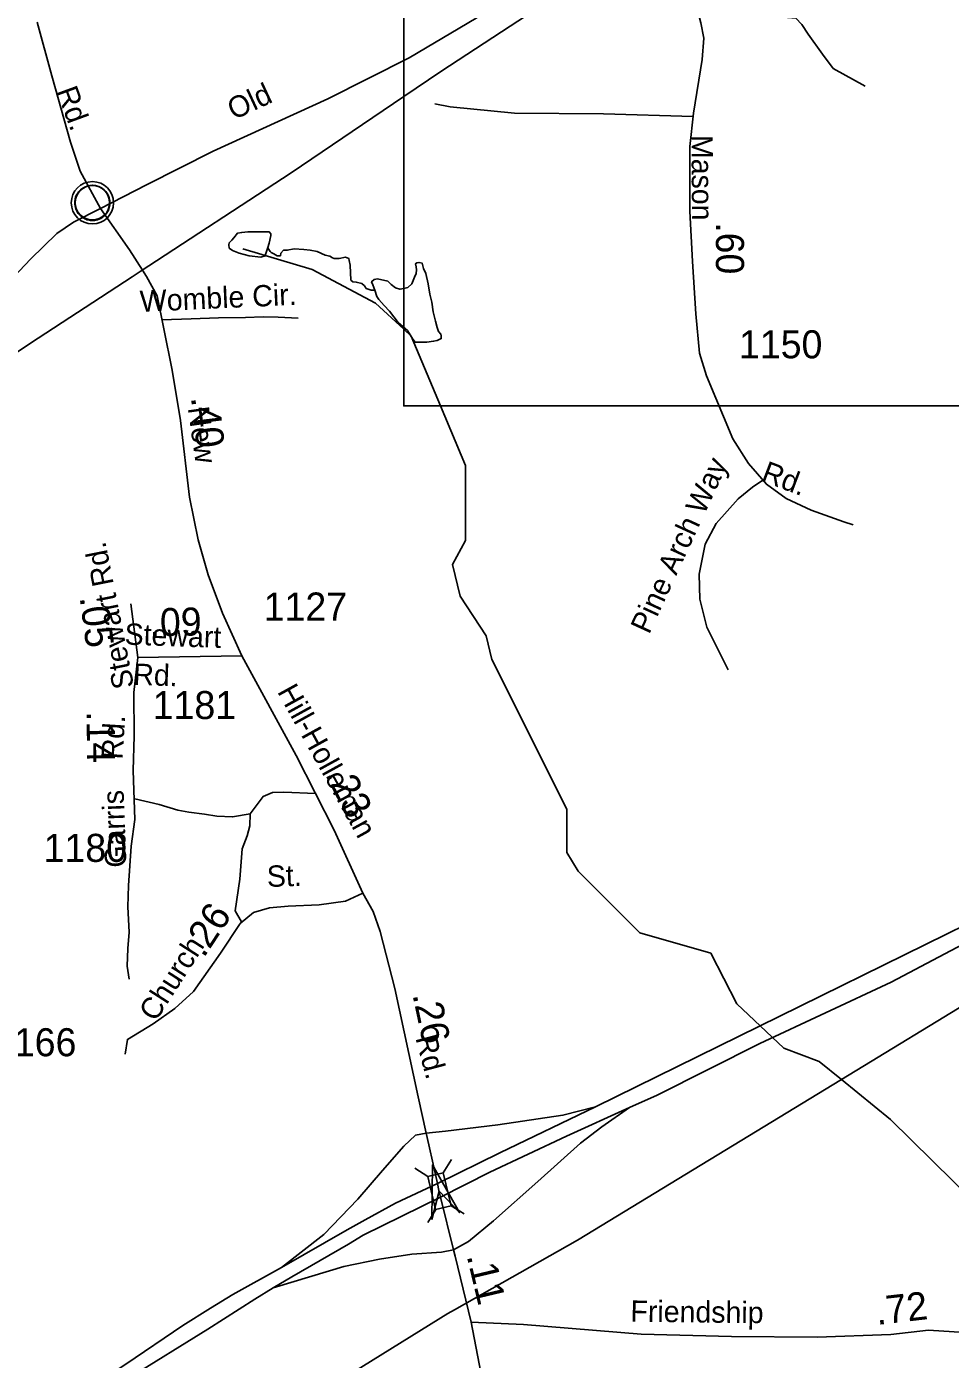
# Model space of a CAD drawing. Extents: x 2001466 to 2224147, y 644118 to 847247.
# Drawn here: x 2018793 to 2022908, y 697641 to 703581 of the extents above; entities that cross this region are included whole.
import ezdxf

# ---------------------------------------------------------------- set-up
doc = ezdxf.new("R2010")
doc.units = 0
for name, color, linetype in [('Exist Civil Demographics Community CELL', 7, 'Continuous'), ('Exist Hydrographic Misc Water Feature', 7, 'Continuous'), ('Exist Railroad Mainline', 7, 'Continuous'), ('Exist Road Non-System Type 51', 7, 'Continuous'), ('Exist Road Non-System Type 51 Label', 7, 'Continuous'), ('Exist Road Primary US Divided Attributed', 7, 'Continuous'), ('Exist Road Primary US Ramp 1 Lane  Attributed', 7, 'Continuous'), ('Exist Road Secondary Mileage Hundredths English Label', 7, 'Continuous'), ('Exist Road Secondary Structure Standard Bridge Attributed CELL', 7, 'Continuous'), ('Exist Road Secondary Structure Standard Bridge CELL', 7, 'Continuous'), ('Exist Road Secondary Type 51 Attributed', 7, 'Continuous'), ('Exist Road Secondary Type 51 Label', 7, 'Continuous'), ('Exist Road Secondary Type 51 Number Label', 7, 'Continuous'), ('Exist Utilities Electrical Transmission Line', 7, 'Continuous'), ('Map Preparation Inset Cut Line', 7, 'Continuous')]:
    doc.layers.add(name, color=color, linetype=linetype)

msp = doc.modelspace()

# ---------------------------------------------------------------- linework, layer by layer
at = {"layer": 'Exist Civil Demographics Community CELL'}
msp.add_lwpolyline([(2019008.1, 702808.4), (2019009.1, 702814), (2019010.9, 702820.6), (2019013.8, 702827.8), (2019016.7, 702833.5), (2019020.1, 702839.3), (2019023.8, 702844.4), (2019027.8, 702848.8), (2019032.4, 702853.4), (2019037.9, 702858), (2019043.3, 702861.6), (2019048.2, 702864.5), (2019053.3, 702866.9), (2019058.7, 702869.2), (2019064.4, 702871.1), (2019068.7, 702872.2), (2019073.5, 702872.9), (2019077.7, 702873.7), (2019084, 702873.9), (2019088.5, 702873.8), (2019094.1, 702873.6), (2019099, 702872.8), (2019103.9, 702871.8), (2019108.9, 702870.4), (2019114.1, 702868.5), (2019120.8, 702865.6), (2019127, 702862.1), (2019132.1, 702858.5), (2019137.3, 702854.5), (2019140.6, 702851.4), (2019144.7, 702847), (2019148.6, 702842.3), (2019151.6, 702837.7), (2019154.8, 702832.7), (2019157.2, 702827.5), (2019159.2, 702822.5), (2019160.8, 702817.5), (2019162.1, 702812.9), (2019163.2, 702806.9), (2019163.8, 702802.2), (2019164.1, 702796.2), (2019163.9, 702790.4), (2019163.3, 702784.7), (2019162.4, 702779.2), (2019160.7, 702773.1), (2019158.9, 702767.2), (2019156.6, 702762.2), (2019153.4, 702756.2), (2019150.1, 702750.8), (2019146.7, 702746.1), (2019142.4, 702741.4), (2019137.1, 702736.4), (2019132.1, 702732.3), (2019127.1, 702728.9), (2019122.8, 702726.4), (2019116, 702723.1), (2019108.8, 702720.4), (2019102.9, 702719), (2019096.3, 702717.7), (2019091.9, 702717.2), (2019087.4, 702716.9), (2019081.8, 702716.9), (2019077.5, 702717.3), (2019071.9, 702718.1), (2019066, 702719.4), (2019061.4, 702720.7), (2019056.2, 702722.6), (2019051.6, 702724.5), (2019047.7, 702726.8), (2019040.9, 702730.9), (2019035.3, 702735.1), (2019030.4, 702739.6), (2019025.9, 702744.5), (2019022.7, 702748.4), (2019019.8, 702752.6), (2019015.7, 702759.7), (2019014, 702763.3), (2019012.2, 702767.3), (2019009.7, 702775.5), (2019008.1, 702782.5), (2019007.4, 702787.7), (2019007.1, 702794), (2019007, 702798.7), (2019007.6, 702805.2)], close=True, dxfattribs=at)
for centre, radius in [((2019085.7, 702796), 94.3), ((2019085.5, 702796.3), 76.7)]:
    msp.add_circle(centre, radius, dxfattribs=at)
at = {"layer": 'Exist Hydrographic Misc Water Feature'}
for points in [[(2019867.4, 702596), (2019857.5, 702566.1), (2019855.5, 702560.1), (2019835.6, 702554.1), (2019783.5, 702560.1), (2019739.4, 702572), (2019709.5, 702584), (2019695.6, 702594), (2019693.5, 702608), (2019695.6, 702618), (2019707.5, 702630), (2019715.4, 702640), (2019731.4, 702660), (2019751.3, 702664), (2019777.4, 702666.1), (2019809.4, 702666.1), (2019837.5, 702666.1), (2019859.4, 702666.1), (2019873.3, 702666.1), (2019881.3, 702658.1), (2019881.3, 702650.1), (2019873.3, 702616.1), (2019867.4, 702596)], [(2020472.9, 702232.5), (2020347.6, 702348.9), (2020064.7, 702499), (2019755.6, 702590.6)], [(2019867.4, 702596), (2019871.5, 702588.2), (2019877.4, 702578.2), (2019881.5, 702574.1), (2019893.4, 702568.1), (2019909.4, 702560.1), (2019923.6, 702560.1)], [(2019923.6, 702560.1), (2019925.4, 702572.1), (2019937.3, 702584.2), (2019953.5, 702584.2), (2019985.3, 702590.2), (2020027.3, 702588.2), (2020055.4, 702584.2), (2020087.4, 702578.2), (2020123.3, 702562.3), (2020143.4, 702558.3), (2020155.5, 702550.3), (2020163.5, 702548.3), (2020185.4, 702548.3), (2020213.3, 702554.3), (2020227.5, 702548.3), (2020229.3, 702538.3), (2020233.4, 702518.3), (2020237.5, 702450.4)], [(2020343.5, 702406.5), (2020335.5, 702430.4), (2020329.6, 702444.4), (2020341.5, 702454.4), (2020355.4, 702456.4), (2020401.6, 702446.5), (2020417.5, 702432.5), (2020435.6, 702416.5), (2020455.5, 702410.5), (2020473.5, 702414.5), (2020491.6, 702418.5), (2020509.4, 702434.5), (2020521.3, 702464.5), (2020527.5, 702480.5), (2020529.3, 702496.5), (2020527.5, 702510.5), (2020525.4, 702524.5), (2020531.4, 702528.5), (2020541.4, 702530.5), (2020555.3, 702526.5), (2020561.3, 702502.5), (2020571.3, 702480.5), (2020581.6, 702434.6), (2020589.6, 702388.6), (2020597.6, 702352.6), (2020603.5, 702310.6), (2020609.5, 702286.6), (2020613.6, 702268.6), (2020621.6, 702240.6), (2020627.5, 702222.6), (2020637.6, 702210.7), (2020639.6, 702202.7), (2020639.6, 702190.7), (2020621.6, 702182.6), (2020605.6, 702178.6), (2020575.6, 702174.6), (2020563.5, 702174.6)], [(2020237.5, 702450.4), (2020245.5, 702444.3), (2020261.5, 702442.3), (2020285.5, 702436.4), (2020297.6, 702426.4), (2020305.6, 702414.4), (2020313.6, 702410.4), (2020327.5, 702406.4), (2020343.5, 702406.5)], [(2020563.5, 702174.6), (2020555.5, 702174.6), (2020551.7, 702174.6), (2020527.7, 702174.5), (2020523.6, 702174.6), (2020513.7, 702188.5), (2020489.7, 702226.5), (2020447.5, 702262.5), (2020409.6, 702312.5), (2020385.6, 702338.4), (2020361.6, 702364.4), (2020353.6, 702378.4), (2020343.5, 702406.5)], [(2020637.1, 701890.9), (2020506.5, 702201.3), (2020472.9, 702232.5)], [(2020748.5, 701290.8), (2020748.7, 701625.4), (2020637.1, 701890.9)], [(2022422.9, 698888.1), (2022324.5, 698968.5), (2022166.4, 699027.5), (2021957.5, 699225.3), (2021840.6, 699450.8), (2021524.6, 699542.5), (2021249.6, 699817.2), (2021199.6, 699900.3), (2021199.6, 700093.8), (2020865.6, 700760.2), (2020840.6, 700865.7), (2020723.7, 701041.9), (2020690.7, 701183.7), (2020748.5, 701290.8)], [(2023158.5, 698226.4), (2023108.4, 698250.4), (2022641.5, 698709.4), (2022422.9, 698888.1)]]:
    msp.add_lwpolyline(points, dxfattribs=at)
at = {"layer": 'Exist Railroad Mainline'}
for points in [[(2019262.5, 702465.7), (2019299.1, 702489.6), (2019971.3, 702930.1), (2020472.9, 703269.2), (2020637.8, 703380.6), (2021290.1, 703808.9), (2021599.5, 704013.4)], [(2014695.2, 699465.6), (2014957.6, 699637.9), (2015969.1, 700295.6), (2016972.6, 700965.2), (2017688.8, 701433.9), (2017826.9, 701523.3), (2018309.5, 701836.1), (2018810.1, 702169.9), (2019262.5, 702465.7)]]:
    msp.add_lwpolyline(points, dxfattribs=at)
at = {"layer": 'Exist Road Non-System Type 51'}
for points in [[(2021788.3, 703630.9), (2021904.1, 703630.9), (2021964, 703630.9), (2022039.8, 703634.8), (2022127.6, 703626.9), (2022219.4, 703618.9), (2022247.3, 703590.9), (2022275.3, 703547), (2022339.1, 703459.1), (2022387, 703395.2), (2022528.6, 703315.3)], [(2020611.9, 703236.7), (2020679, 703224), (2020966.8, 703195.2), (2021363.3, 703192), (2021762.2, 703180.9)], [(2019395.6, 702273.9), (2019525.3, 702279.3), (2019647.5, 702283.3), (2019767.3, 702285.3), (2019846.6, 702287.3), (2019912.9, 702286.4), (2020002.7, 702282.2)], [(2021918.3, 700714), (2021824, 700904.7), (2021792.6, 701028.6), (2021788.7, 701140.6), (2021816.2, 701274.3), (2021865.3, 701366.7), (2021963.5, 701476.8), (2022026.4, 701527.9), (2022072.9, 701559.7)], [(2019788.3, 700071.7), (2019710.2, 700058.5), (2019640.3, 700062.4), (2019584.3, 700070.3), (2019514.8, 700079.9), (2019466.2, 700089.2), (2019383.5, 700114.6), (2019274, 700139.2)], [(2020079.8, 700163.4), (2019938.3, 700168.3), (2019887.5, 700167.7), (2019846.2, 700149.1), (2019788.3, 700071.7)], [(2019788.3, 700071.7), (2019787.4, 700018.4), (2019774.7, 699973.6), (2019752.3, 699916.1), (2019742.7, 699781.7), (2019721.3, 699639.6), (2019749.4, 699591.4)], [(2019274, 700047.7), (2019258.8, 699928.9), (2019246.6, 699752.3), (2019243.6, 699657.9), (2019249.7, 699545.2), (2019243.6, 699472.1), (2019240.5, 699393), (2019249.7, 699335.1)]]:
    msp.add_lwpolyline(points, dxfattribs=at)
at = {"layer": 'Exist Road Primary US Divided Attributed'}
for points in [[(2029594.3, 703535.4), (2029470.7, 703458.2), (2028875.7, 703094.4), (2028744.5, 703014.5), (2028584.6, 702916.2), (2027863, 702478.6), (2027674.7, 702363), (2027348.5, 702163.1), (2026826.3, 701846.7), (2026331, 701548), (2026138.2, 701428.1), (2025345.1, 700942), (2024527, 700439.3), (2024299.1, 700299.1), (2023889.6, 700058.2), (2023801.5, 700007), (2023463.1, 699824.5), (2023169.6, 699672.1), (2022239.9, 699214.9), (2021326.9, 698766.1)], [(2021478.6, 698762.7), (2021601.9, 698818.7), (2022060, 699049), (2022644.6, 699321.5), (2023865.5, 699967.6), (2024300.3, 700232.4), (2024445.7, 700324), (2024644.7, 700441.7), (2025337.6, 700865.2), (2025429.3, 700924.6), (2026516.5, 701580.8), (2026634.6, 701659.9), (2027380.7, 702113.6), (2027700.2, 702307.1), (2028342.2, 702702.5), (2028570.3, 702839.6), (2028768.1, 702960.7), (2029256.1, 703260.4), (2029519.5, 703418.8), (2029577.8, 703456.8)], [(2021326.9, 698766.1), (2020900.6, 698561.5), (2020622.8, 698425.3)], [(2020636.7, 698363.5), (2020856.8, 698475.5), (2021197.6, 698634.9), (2021478.6, 698762.7)], [(2020622.8, 698425.3), (2020436.5, 698337.6), (2020300.5, 698263.3), (2020220.2, 698218.8), (2019927.7, 698050.8)], [(2019890.4, 697959.1), (2019973.8, 698008.1), (2020099.8, 698082), (2020226.7, 698154.8), (2020292.1, 698194.3), (2020636.7, 698363.5)], [(2019927.7, 698050.8), (2019711.5, 697929.8), (2019611.8, 697868.6), (2019488.3, 697791.6), (2019234.1, 697619.4), (2018843.7, 697362.1), (2018321.8, 697033.1), (2018196.5, 696955.5), (2018051.3, 696858.8), (2017678.1, 696619), (2016354.4, 695769)], [(2016373.5, 695712.3), (2017274, 696290), (2017463.2, 696417.8), (2017697.5, 696558.6), (2018092.1, 696817.1), (2018220.2, 696897.8), (2019245.1, 697555.7), (2019599.3, 697775.8), (2019809, 697909.2), (2019890.4, 697959.1)]]:
    msp.add_lwpolyline(points, dxfattribs=at)
at = {"layer": 'Exist Road Primary US Ramp 1 Lane  Attributed'}
for points in [[(2021326.9, 698766.1), (2021182, 698729), (2020892.2, 698686.7), (2020658.5, 698657.5), (2020572.5, 698648.9)], [(2020695.2, 698129.6), (2020761.8, 698165.9), (2020873, 698258.6), (2021071, 698434), (2021260.7, 698604.6), (2021354.8, 698677.7), (2021478.6, 698762.7)], [(2020572.5, 698648.9), (2020525.4, 698639.6), (2020473.3, 698590.9), (2020377.6, 698482), (2020268.1, 698355.3), (2020116.9, 698197.8), (2019927.7, 698050.8)], [(2019890.4, 697959.1), (2020063.8, 698011.6), (2020206.5, 698054.7), (2020364.4, 698087.2), (2020508.2, 698109.1), (2020640.4, 698118), (2020695.2, 698129.6)]]:
    msp.add_lwpolyline(points, dxfattribs=at)
at = {"layer": 'Exist Road Secondary Structure Standard Bridge Attributed CELL'}
msp.add_lwpolyline([(2020598.3, 698264.1), (2020601.2, 698507.9), (2020720.6, 698295.3), (2020631.4, 698389.8)], close=True, dxfattribs=at)
at = {"layer": 'Exist Road Secondary Structure Standard Bridge CELL'}
for p, q in [((2020685.1, 698531.2), (2020648.9, 698472.5)), ((2020521.5, 698492.4), (2020580.2, 698456.2)), ((2020616.2, 698309.5), (2020580, 698250.7)), ((2020683.4, 698325.4), (2020742.1, 698289.1))]:
    msp.add_line(p, q, dxfattribs=at)
msp.add_lwpolyline([(2020648.9, 698472.5), (2020683.7, 698325.4), (2020615, 698309.2), (2020580.2, 698456.2)], close=True, dxfattribs=at)
at = {"layer": 'Exist Road Secondary Type 51 Attributed'}
for points in [[(2021484.2, 704078.9), (2021234.5, 703917.6), (2020795.8, 703619.1), (2020496.6, 703441.9), (2020134.5, 703259.9), (2019623.1, 703026.8), (2019326.4, 702876.7), (2019122.1, 702770.6)], [(2021599.5, 704013.4), (2021639.8, 703959.2), (2021714.7, 703829.8), (2021777, 703671.8), (2021797.3, 703598.3), (2021810.1, 703530.5), (2021802.1, 703434.7), (2021763.8, 703195.2), (2021747.4, 703046.7), (2021748.2, 702759.4), (2021759.4, 702534.2), (2021774.2, 702301.1), (2021790.9, 702125.5), (2021821.2, 702024.9), (2021938.9, 701743.2), (2022009.1, 701633.8), (2022088.9, 701541.2), (2022176.6, 701477.3), (2022288.3, 701426.2), (2022433.5, 701373.6), (2022475.3, 701360.4)], [(2019122.1, 702770.6), (2019030.7, 702937.4), (2018987.7, 703066.7), (2018905.5, 703362.1), (2018840.1, 703601.5)], [(2019122.1, 702770.6), (2019002, 702709.1), (2018927.1, 702659.6), (2018809, 702544.6), (2018482.7, 702199.8), (2018165.2, 701891.6), (2018001.7, 701732), (2017756, 701561.2), (2017515.1, 701385.5), (2017363.5, 701297.7), (2017145.8, 701222.7), (2016616.1, 701085.4), (2016233.2, 701005.6), (2015737.8, 700905), (2015517.6, 700857.1), (2015346.9, 700788.4), (2015198.6, 700697.4), (2015069.3, 700582.5), (2014875.5, 700360.6), (2014759, 700218.5)], [(2019308.5, 702495.7), (2019250.1, 702587), (2019122.1, 702770.6)], [(2019750.7, 700777.3), (2019664.5, 700967.3), (2019601.5, 701138.1), (2019556.8, 701293), (2019518.5, 701484.6), (2019477.9, 701826.2), (2019441.2, 702049.7), (2019403.3, 702234.9), (2019374.6, 702381), (2019326.7, 702467.2), (2019308.5, 702495.7)], [(2019256.1, 701008), (2019288, 700768.5)], [(2019750.7, 700777.3), (2019288, 700768.5)], [(2020290.7, 699718.8), (2020163.1, 699999.8), (2019994, 700331.9), (2019750.7, 700777.3)], [(2019288, 700768.5), (2019269.9, 700613.6), (2019272, 700420.5), (2019267.9, 700265.4), (2019274, 700047.7)], [(2020290.7, 699718.8), (2020212.9, 699683.7), (2020096.5, 699666.1), (2019957.7, 699661.3), (2019874.7, 699653.4), (2019802.9, 699632.6), (2019743.9, 699583.1), (2019656.1, 699450.6), (2019535.3, 699279.8), (2019453.1, 699204.7), (2019356.6, 699136.1), (2019241.3, 699066.6), (2019231, 699000.4)], [(2020572.5, 698648.9), (2020536.4, 698810.4), (2020433.5, 699294.2), (2020368.1, 699548), (2020337, 699637.4), (2020290.7, 699718.8)], [(2020622.8, 698425.3), (2020584.3, 698596.5), (2020572.5, 698648.9)], [(2020636.7, 698363.5), (2020629.8, 698392.9), (2020622.8, 698425.3)], [(2020695.2, 698129.6), (2020636.7, 698363.5)], [(2020772.6, 697806.6), (2020702.4, 698101.3), (2020695.2, 698129.6)], [(2021174.7, 696644.6), (2021041.7, 696934), (2020909.8, 697272.1), (2020831.7, 697504.5), (2020772.6, 697806.6)], [(2023538.9, 697709.3), (2023365.7, 697724.2), (2023017.3, 697758), (2022810.4, 697770.7), (2022643.7, 697751.7), (2022314.3, 697739), (2021933.2, 697743.2), (2021530, 697753.8), (2021006.4, 697796), (2020772.6, 697806.6)]]:
    msp.add_lwpolyline(points, dxfattribs=at)
at = {"layer": 'Exist Utilities Electrical Transmission Line'}
msp.add_line((2023434.6, 699504), (2022422.9, 698888.1), dxfattribs=at)
for points in [[(2022422.9, 698888.1), (2021246.9, 698172.2), (2020699.4, 697861.6)], [(2020699.4, 697861.6), (2020669.6, 697844.7), (2018205.4, 696316.2)]]:
    msp.add_lwpolyline(points, dxfattribs=at)
at = {"layer": 'Map Preparation Inset Cut Line'}
for p, q in [((2020472.9, 703473), (2020472.9, 706915.1)), ((2020472.9, 703269.2), (2020472.9, 703473)), ((2020472.9, 703145.9), (2020472.9, 703269.2)), ((2020472.9, 702232.5), (2020472.9, 703145.9)), ((2021830, 701890.9), (2020637.1, 701890.9)), ((2023349.4, 701890.9), (2021830, 701890.9))]:
    msp.add_line(p, q, dxfattribs=at)
msp.add_lwpolyline([(2020637.1, 701890.9), (2020472.9, 701890.9), (2020472.9, 702232.5)], dxfattribs=at)

# ---------------------------------------------------------------- texts
at = {"layer": 'Exist Road Non-System Type 51 Label'}
for s, rotation, p in [('Womble Cir.', 2.61401, (2019299.1, 702309.4)), ('Pine Arch Way', 65.25248, (2021565.9, 700869.1))]:
    msp.add_text(s, height=95, rotation=rotation, dxfattribs=at).set_placement(p)
at = {"layer": 'Exist Road Secondary Mileage Hundredths English Label'}
for s, rotation, p in [('.60', 270, (2021864, 702709.5)), ('.40', 276.79051, (2019524.3, 701928.5)), ('.05', 277.58954, (2019028.5, 701037.3)), ('.09', 1.08741, (2019341, 700863.2)), ('.14', 270.6307, (2019059.5, 700530.2)), ('.23', 296.98803, (2020120.9, 700249.3)), ('.26', 56.48765, (2019581.4, 699426.8)), ('.26', 282.00914, (2020511.3, 699266.5)), ('.11', 283.39746, (2020752.8, 698102.1)), ('.72', 6.50373, (2022581.8, 697794.1))]:
    msp.add_text(s, height=125, rotation=rotation, dxfattribs=at).set_placement(p)
at = {"layer": 'Exist Road Secondary Type 51 Label'}
for s, rotation, p in [('Old', 24.92212, (2019715.4, 703163.9)), ('Rd.', 290.14097, (2018923.9, 703294.8)), ('Mason', 270.36524, (2021754.9, 703098.2)), ('New', 278.12672, (2019510.1, 701881.3)), ('Rd.', 339.29846, (2022060.8, 701558.1)), ('Stewart Rd.', 101.21849, (2019271.8, 700639.4)), ('Stewart', 357.97108, (2019227.8, 700827)), ('Rd.', 357.97108, (2019266.5, 700647.8)), ('Hill-Holleman', 298.86494, (2019907.4, 700617.5)), ('Rd.', 86.42509, (2019219.6, 700313)), ('Garris', 92.16308, (2019237.5, 699834.4)), (' St.', 1.97567, (2019829.1, 699744.9)), ('Church', 57.2761, (2019367, 699141.7)), ('Rd.', 284.92554, (2020524.2, 699073.7)), ('Friendship', 359.35481, (2021482.6, 697808.5))]:
    msp.add_text(s, height=95, rotation=rotation, dxfattribs=at).set_placement(p)
at = {"layer": 'Exist Road Secondary Type 51 Number Label'}
for s, p in [('1150', (2021966.5, 702102.8)), ('1127', (2019848.6, 700933.9)), ('1181', (2019354.1, 700494.8)), ('1180', (2018868, 699858.2)), ('1166', (2018642.4, 698991.8))]:
    msp.add_text(s, height=125, dxfattribs=at).set_placement(p)

doc.saveas('drawing.dxf')
